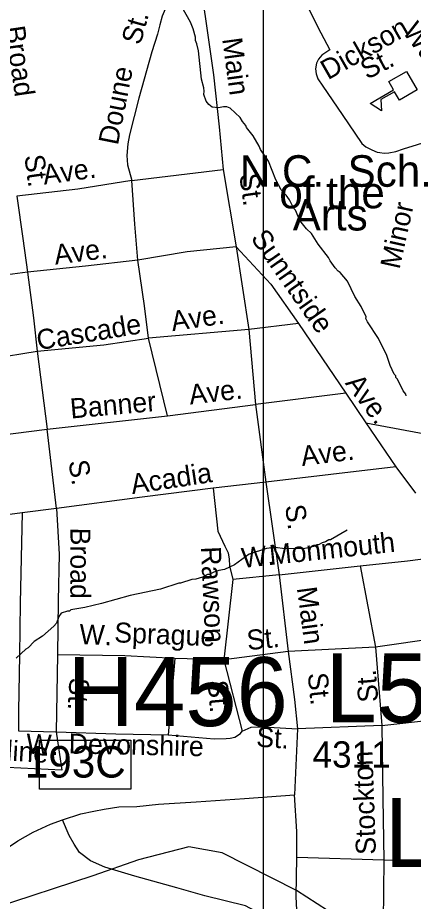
# Model space of a CAD drawing. Extents: x 1547597 to 1699558, y 810033 to 920809.
# Drawn here: x 1632554 to 1634436, y 845325 to 849529 of the extents above; entities that cross this region are included whole.
import ezdxf

# ---------------------------------------------------------------- set-up
doc = ezdxf.new("R2010")
doc.units = 0
for name, color, linetype in [('Exist Cultural Educational Facility High CELL', 7, 'Continuous'), ('Exist Cultural Educational Facility High Label', 7, 'Continuous'), ('Exist Hydrographic Creek Single Shore', 7, 'Continuous'), ('Exist Hydrographic Misc Water Feature', 7, 'Continuous'), ('Exist Road Non-System Type 51', 7, 'Continuous'), ('Exist Road Non-System Type 51 Label', 7, 'Continuous'), ('Exist Road Primary Interstate Interchange CELL', 7, 'Continuous'), ('Exist Road Primary Interstate Ramp 1 Lane Attributed', 7, 'Continuous'), ('Exist Road Primary Interstate Structure Cantilever Sign Number Label', 7, 'Continuous'), ('Exist Road Primary US Structure Non-Sys NCDOT Number Label', 7, 'Continuous'), ('Exist Road Secondary Type 51 Attributed', 7, 'Continuous'), ('Exist Road Secondary Type 51 Number Label', 7, 'Continuous'), ('Exist Road Secondary Type 51 Undivided 4 Lane Attributed', 7, 'Continuous'), ('Map Preparation Inset Cut Line', 7, 'Continuous')]:
    doc.layers.add(name, color=color, linetype=linetype)

msp = doc.modelspace()

# ---------------------------------------------------------------- linework, layer by layer
at = {"layer": 'Exist Cultural Educational Facility High CELL'}
msp.add_lwpolyline([(1634455.3, 849185.9), (1634370.4, 849137.1), (1634347.5, 849177), (1634282.4, 849139.6), (1634284.8, 849086.7), (1634231.2, 849121.3), (1634342.7, 849185.3), (1634319.7, 849225.2), (1634404.7, 849274)], close=True, dxfattribs=at)
at = {"layer": 'Exist Hydrographic Creek Single Shore'}
msp.add_lwpolyline([(1639777.9, 843989.4), (1638758, 844518.9), (1638485, 844623), (1638168, 844668.8), (1637703.9, 844858.7), (1637498, 845092.7), (1637356.9, 845144.8), (1637072.9, 845124.3), (1636906, 845032.6), (1636378.9, 844915.2), (1635732.9, 844680.2), (1635497.4, 844667.4), (1635292.9, 844720.6), (1634628.9, 844937.6), (1634175.6, 845186.2), (1633880.8, 845376.5), (1633527.5, 845554.8), (1633368.4, 845583.5), (1633129.8, 845522.9), (1632911.4, 845446.3), (1632436.5, 845291.3), (1631850.8, 845054.7)], dxfattribs=at)
at = {"layer": 'Exist Hydrographic Misc Water Feature'}
for points in [[(1634402.5, 847729.4), (1634400.5, 847737.4), (1634388.8, 847753.5), (1634361.2, 847809.7), (1634353.2, 847817.7), (1634353.3, 847825.7), (1634345.3, 847833.8), (1634325.6, 847873.9), (1634310, 847922), (1634270.5, 848002.3), (1634219.2, 848082.6), (1634211.3, 848098.6), (1634211.4, 848106.6), (1634187.7, 848154.8), (1634158.1, 848203), (1634122.7, 848275.2), (1634089, 848317.5), (1634079, 848323.6), (1634065.2, 848339.7), (1634041.4, 848371.8), (1634033.5, 848387.9), (1633984, 848452.3), (1633952.4, 848502.4), (1633928.6, 848524.6), (1633896.9, 848564.9), (1633875.3, 848613), (1633867.3, 848621.1), (1633847.6, 848663.2), (1633831.8, 848685.3), (1633808, 848709.4), (1633782.4, 848757.6), (1633747, 848845.9), (1633709.4, 848902.1), (1633703.6, 848918.1), (1633673.9, 848966.4), (1633642.3, 849006.6), (1633640.3, 849016.6), (1633624.5, 849034.7), (1633612.6, 849054.8), (1633565, 849099.1), (1633549.1, 849105.2), (1633533.1, 849105.4), (1633509.1, 849099.6), (1633479.1, 849103.8), (1633463.2, 849116), (1633451.4, 849132.1), (1633439.6, 849164.1), (1633441.7, 849180.1), (1633439.8, 849196.1), (1633428.1, 849236.2), (1633415.1, 849372.2), (1633407.3, 849404.2), (1633399.4, 849420.3), (1633399.5, 849436.3), (1633389.8, 849476.3), (1633376.1, 849508.4), (1633334.6, 849580.7)], [(1634122.3, 847090.1), (1634042.1, 847044.8), (1634034.1, 847044.8), (1634018, 847035), (1634002, 847031.1), (1633985.9, 847021.3), (1633977.9, 847021.3), (1633961.9, 847013.5), (1633914, 847001.9), (1633874, 847004.2), (1633826, 847002.5), (1633778.1, 847008.9), (1633738.1, 847003.3), (1633656, 846975.9), (1633585.7, 846926.6), (1633537.6, 846902.9), (1633511.5, 846899.1), (1633487.5, 846891.4), (1633465.5, 846879.6), (1633457.5, 846879.6), (1633433.4, 846867.8), (1633401.4, 846858.1), (1633383.4, 846856.2), (1633329.3, 846838.7), (1633321.4, 846838.8), (1633233.3, 846809.5), (1633089.1, 846780.7), (1632953.1, 846741.8), (1632873, 846722.4), (1632807, 846711), (1632800.9, 846705), (1632791, 846705.1), (1632760.9, 846695.4), (1632750.8, 846679.4), (1632738.6, 846647.6), (1632726.5, 846633.7), (1632672.3, 846586.1), (1632632.1, 846560.5), (1632603.9, 846530.7), (1632593.8, 846524.8), (1632547.6, 846481.2)]]:
    msp.add_lwpolyline(points, dxfattribs=at)
at = {"layer": 'Exist Road Non-System Type 51'}
for p, q in [((1633096.9, 848755.1), (1633531.9, 848807.5)), ((1633531.9, 848807.5), (1633593.5, 848438.3)), ((1633593.5, 848438.3), (1633654, 848045)), ((1632601.7, 848319.2), (1632177.4, 848260.8)), ((1633890.3, 848073.4), (1633654, 848045)), ((1633890.3, 848073.4), (1634115.3, 847743.3)), ((1633654, 848045), (1633176.9, 848004.5)), ((1633654, 848045), (1633685.9, 847688.2)), ((1633267.5, 847635), (1633176.9, 848004.5)), ((1632647, 847942.1), (1632694.3, 847570.9)), ((1634115.3, 847743.3), (1633685.9, 847688.2)), ((1634115.3, 847743.3), (1634211, 847601.1)), ((1633267.5, 847635), (1633685.9, 847688.2)), ((1633685.9, 847688.2), (1633735.2, 847319.5)), ((1632694.3, 847570.9), (1633267.5, 847635)), ((1634211, 847601.1), (1634353.2, 847392.1)), ((1634211, 847601.1), (1634753.5, 847499.5)), ((1632185.4, 847506.5), (1632694.3, 847570.9)), ((1632738.7, 847193.2), (1632694.3, 847570.9)), ((1634353.2, 847392.1), (1633735.2, 847319.5)), ((1634353.2, 847392.1), (1634446, 847267.2)), ((1633735.2, 847319.5), (1633484.1, 847290.2)), ((1633735.2, 847319.5), (1633799, 846878.2)), ((1632738.7, 847193.2), (1632575.7, 847172.9)), ((1632575.7, 847172.9), (1632186.9, 847122.9)), ((1633799, 846878.2), (1634183.8, 846921.1)), ((1634183.8, 846921.1), (1634255.8, 846534)), ((1633577.2, 846856.3), (1633535.6, 846473.8)), ((1633799, 846878.2), (1633577.2, 846856.3)), ((1633799, 846878.2), (1633841.8, 846513.3)), ((1633841.8, 846513.3), (1633535.6, 846473.8)), ((1634255.8, 846534), (1633841.8, 846513.3)), ((1634255.8, 846534), (1634286.1, 846161.6)), ((1632743.7, 846497.8), (1632737.9, 846130.5)), ((1633301.2, 846479.5), (1633269.7, 846116.2)), ((1633535.6, 846473.8), (1633301.2, 846479.5)), ((1633535.6, 846473.8), (1633622, 846133.8)), ((1632737.9, 846130.5), (1632763.6, 845949.2)), ((1634286.1, 846161.6), (1633884.8, 846146)), ((1634296.1, 845521.4), (1633881.5, 845533.9)), ((1634296.1, 845521.4), (1634293.6, 845229.5)), ((1634685.9, 845511.5), (1634296.1, 845521.4))]:
    msp.add_line(p, q, dxfattribs=at)
for points in [[(1633402.9, 849834), (1633371.7, 849773), (1633333.5, 849709.2), (1633274, 849612.8), (1633255.6, 849570.3), (1633241.4, 849536.3), (1633230.1, 849495.1), (1633218.7, 849451.2), (1633193.2, 849366.1), (1633130.9, 849146.9), (1633086.9, 848972.5), (1633078.4, 848928.6), (1633074.2, 848873.3), (1633077, 848829.4), (1633096.9, 848755.1)], [(1633402.9, 849834), (1633485.1, 849257), (1633513.4, 849010.3), (1633531.9, 848807.5)], [(1633927.4, 849596.9), (1633981.8, 849483.9), (1634040, 849377.1)], [(1634040, 849377.1), (1634001.7, 849351.7), (1633985.5, 849332), (1633975.1, 849312.2), (1633970.8, 849286.3), (1633974.3, 849262.2), (1633982, 849238), (1634005.5, 849203.7), (1634097.4, 849068.4), (1634191.3, 848930.8), (1634210.9, 848914.6), (1634238.7, 848900.2), (1634264.5, 848889.7), (1634276.4, 848887.6), (1634298.4, 848885.2), (1634320, 848886.3), (1634352.6, 848892.5), (1634389.2, 848904.5), (1634523.3, 848945.8)], [(1633096.9, 848755.1), (1632839.7, 848713.4), (1632550.6, 848679.4)], [(1633125.9, 848376), (1633111.7, 848546.1), (1633096.9, 848755.1)], [(1632550.6, 848679.4), (1632579, 848478), (1632601.7, 848319.2)], [(1633593.5, 848438.3), (1633361.1, 848415.7), (1633125.9, 848376)], [(1633593.5, 848438.3), (1633757.8, 848261.6), (1633890.3, 848073.4)], [(1633125.9, 848376), (1632876.5, 848347.6), (1632601.7, 848319.2)], [(1633176.9, 848004.5), (1633157.1, 848157.6), (1633125.9, 848376)], [(1632601.7, 848319.2), (1632630, 848100.9), (1632647, 847942.1)], [(1632647, 847942.1), (1632964.4, 847973.3), (1633176.9, 848004.5)], [(1632185.9, 847883.7), (1632431.6, 847908.1), (1632647, 847942.1)], [(1633484.1, 847290.2), (1633146.8, 847247.3), (1632738.7, 847193.2)], [(1633484.1, 847290.2), (1633506.8, 847085.5), (1633539.8, 847015), (1633555.2, 846982.7), (1633560.8, 846952.7), (1633562.3, 846920.7), (1633577.2, 846856.3)], [(1632738.7, 847193.2), (1632752.2, 846977.3), (1632746.5, 846754.1), (1632743.7, 846497.8)], [(1632575.7, 847172.9), (1632566.4, 846742.7), (1632563.5, 846496.7), (1632557.8, 846230.6), (1632557.8, 846136.2), (1632737.9, 846130.5)], [(1634183.8, 846921.1), (1634408.3, 846945.5), (1634470.2, 846952.7), (1634502.3, 846956), (1634524.4, 846957.8), (1634538.4, 846957.5), (1634584.3, 846952.7), (1634688, 846943.2)], [(1634892.5, 846598.1), (1634816.8, 846605.2), (1634752.7, 846602.3), (1634672.6, 846593.6), (1634554.5, 846577.3), (1634255.8, 846534)], [(1633841.8, 846513.3), (1633871.6, 846285), (1633884.8, 846146)], [(1633301.2, 846479.5), (1633063.9, 846492.1), (1632743.7, 846497.8)], [(1634286.1, 846161.6), (1634542.4, 846189.6), (1634812.6, 846213.3)], [(1632737.9, 846130.5), (1633021, 846121.9), (1633269.7, 846116.2)], [(1633269.7, 846116.2), (1633489.6, 846097.9), (1633545.4, 846099), (1633565.5, 846100.8), (1633587.6, 846106.3), (1633614, 846124), (1633622, 846133.8)], [(1633622, 846133.8), (1633664.4, 846153.2), (1633700.2, 846154.7), (1633748.2, 846153.9), (1633884.8, 846146)], [(1633884.8, 846146), (1633871.2, 845831.7)], [(1634286.1, 846161.6), (1634290.6, 845813.5), (1634296.1, 845521.4)], [(1632763.6, 845949.2), (1632503.9, 845961.1), (1632214.3, 845979.5)]]:
    msp.add_lwpolyline(points, dxfattribs=at)
at = {"layer": 'Exist Road Primary Interstate Interchange CELL'}
msp.add_lwpolyline([(1632657.5, 846091.9), (1633092.4, 846091.9), (1633092.4, 845858.7), (1632657.5, 845858.7)], close=True, dxfattribs=at)
at = {"layer": 'Exist Road Primary Interstate Ramp 1 Lane Attributed'}
msp.add_lwpolyline([(1633729.4, 845254.3), (1633638.1, 845303.1), (1633443.8, 845351), (1633311.6, 845389), (1633111.1, 845443.7), (1632968.4, 845487.8), (1632900, 845516.7), (1632848.4, 845557.7), (1632822.5, 845597.3), (1632799.8, 845638.3), (1632767, 845713.2)], dxfattribs=at)
at = {"layer": 'Exist Road Secondary Type 51 Attributed'}
msp.add_lwpolyline([(1633885.6, 845218.3), (1633878.9, 845347.6), (1633881.5, 845533.9), (1633881.5, 845656.3), (1633871.2, 845831.7)], dxfattribs=at)
at = {"layer": 'Exist Road Secondary Type 51 Undivided 4 Lane Attributed'}
for points in [[(1632767, 845713.2), (1632854.2, 845741.1), (1632916.5, 845754.3), (1632965.5, 845763.8), (1633035.5, 845773.8), (1633120.5, 845775.6), (1633224.2, 845786.4), (1633403.6, 845797.8), (1633633.9, 845814.8), (1633871.2, 845831.7)], [(1631069.9, 845128.2), (1631457.3, 845120.6), (1631600.1, 845114.4), (1631687.5, 845114.4), (1631742.9, 845114.4), (1631806.9, 845126.8), (1631913.5, 845155.7), (1631977.4, 845180.5), (1632035, 845207.4), (1632139.4, 845279.8), (1632256.7, 845379.1), (1632405.9, 845505.3), (1632486.9, 845567.3), (1632555.1, 845612.9), (1632627.6, 845654.2), (1632710.7, 845691.5), (1632767, 845713.2)]]:
    msp.add_lwpolyline(points, dxfattribs=at)
at = {"layer": 'Map Preparation Inset Cut Line'}
for points in [[(1633724, 874749.3), (1571208, 874749.3), (1571208, 831307.2), (1633724, 831307.2)], [(1694128.9, 831307.2), (1633724, 831307.2), (1633724, 874749.3), (1694128.9, 874749.3)]]:
    msp.add_lwpolyline(points, close=True, dxfattribs=at)

# ---------------------------------------------------------------- texts
at = {"layer": 'Exist Cultural Educational Facility High Label'}
for s, p in [('N.C.  Sch.', (1633611.1, 848724.8)), ('of the', (1633798.8, 848622.3)), ('Arts', (1633862.8, 848516.8))]:
    msp.add_text(s, height=150, dxfattribs=at).set_placement(p)
at = {"layer": 'Exist Road Non-System Type 51 Label'}
for s, rotation, p in [('St.', 74.4953, (1633137.8, 849395.5)), ('Dickson', 29.6407, (1634030.3, 849231)), ('Waughtown', 307.2914, (1634380.7, 849462.6)), ('Broad', 278.2243, (1632493.4, 849484.2)), ('Main', 277.7309, (1633526.8, 849428.4)), ('St.', 27.333, (1634216.1, 849233)), ('Doune', 78.9024, (1633030.8, 848919.4)), ('St.', 277.8374, (1632585.5, 848872)), ('Ave.', 7.8968, (1632679.9, 848734.4)), ('St.', 278.0863, (1633608.1, 848782.1)), ('Minor', 77.5253, (1634370.5, 848329.1)), ('Sunntside', 305.1379, (1633659.9, 848480)), ('Ave.', 7.2505, (1632733.3, 848354.1)), ('Cascade', 9.2515, (1632652.3, 847947.1)), ('Ave.', 8.3633, (1633290.6, 848037.4)), ('Ave.', 306.7693, (1634109.4, 847789.5)), ('Ave.', 6.7038, (1633374.6, 847688)), ('Banner', 5.0729, (1632807.7, 847621.8)), ('Ave.', 7.1831, (1633907.4, 847395.6)), ('S.', 279.1971, (1632795.3, 847418)), ('Acadia', 8.5694, (1633099.6, 847262.3)), ('S.', 277.6961, (1633825.9, 847207.2)), ('Broad', 269.8741, (1632805.4, 847102.9)), ('Monmouth', 6.0987, (1633756.3, 846924.9)), ('W.', 6.0761, (1633624.1, 846910.8)), ('Rawson', 272.6052, (1633425.8, 847011.6)), ('Main', 277.6111, (1633882, 846815.8)), ('W.', 357.7083, (1632846.4, 846549)), ('Sprague', 357.6825, (1633012.5, 846557.5)), ('St.', 6.0521, (1633649.1, 846519.4)), ('St.', 266.5192, (1632801.4, 846390.8)), ('St.', 275.8289, (1633933.6, 846408.6)), ('St.', 94.7876, (1634270.2, 846275.6)), ('St.', 274.6572, (1633457.7, 846373.8)), ('St.', 356.2915, (1633687.1, 846061)), ('Brookline', 356.3464, (1632168.2, 846016.6)), ('W.', 357.1219, (1632592.4, 846028.2)), ('Devonshire', 358.7638, (1632796.2, 846028.7)), ('Stockton', 91.9881, (1634258.9, 845547.9))]:
    msp.add_text(s, height=95, rotation=rotation, dxfattribs=at).set_placement(p)
at = {"layer": 'Exist Road Primary Interstate Interchange CELL'}
msp.add_text('193C', height=150, dxfattribs=at).set_placement((1632588.8, 845913.6))
at = {"layer": 'Exist Road Primary Interstate Structure Cantilever Sign Number Label'}
for s, p in [('L514', (1634018, 846175.9)), ('L516', (1634300.1, 845488.5))]:
    msp.add_text(s, height=328.08, dxfattribs=at).set_placement(p)
at = {"layer": 'Exist Road Primary US Structure Non-Sys NCDOT Number Label'}
msp.add_text('H456', height=328.08, dxfattribs=at).set_placement((1632790.6, 846158.6))
at = {"layer": 'Exist Road Secondary Type 51 Number Label'}
msp.add_text('4311', height=125, dxfattribs=at).set_placement((1633957, 845961.2))

doc.saveas('drawing.dxf')
